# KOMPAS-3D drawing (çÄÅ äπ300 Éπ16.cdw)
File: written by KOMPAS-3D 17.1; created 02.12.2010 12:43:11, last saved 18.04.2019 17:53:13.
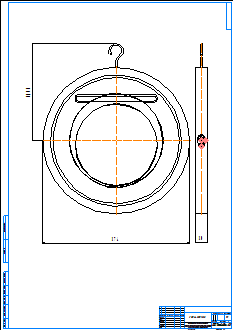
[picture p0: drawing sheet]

Sheet 1: A1, portrait

Title block, sheet 1: name: ЗОП Ду300 Ру16; material: Внимание! Данный продукт является объектом авторского права ООО «Торговый Дом АДЛ». / Запрещается изменение, копирование, распространение / (в том числе путем копирования на другие сайты и ресурсы в Интернете) / или любое иное использование информации и объектов без предварительного / согласия правообладателя (ООО «Торговый Дом АДЛ»).; scale: 1:1; sheets: 1; organisation: ООО "Торговый дом АДЛ"; sheet format: A1; stored path: \\adlc.lan\data\АДЛ_ПКД\3D-модели\ADL production\Клапаны обратные ГРАНЛОК\ЗОП\KOMPAS 2D\ЗОП Ду300 Ру16.cdw

Views: Спереди 1, Проекционный вид 2
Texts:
  bsv
  adl
Dimensions and other numbers on the sheet: 374; 30; 247,2; 1:1; 1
